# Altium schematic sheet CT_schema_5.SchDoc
size 367 x 333 mm
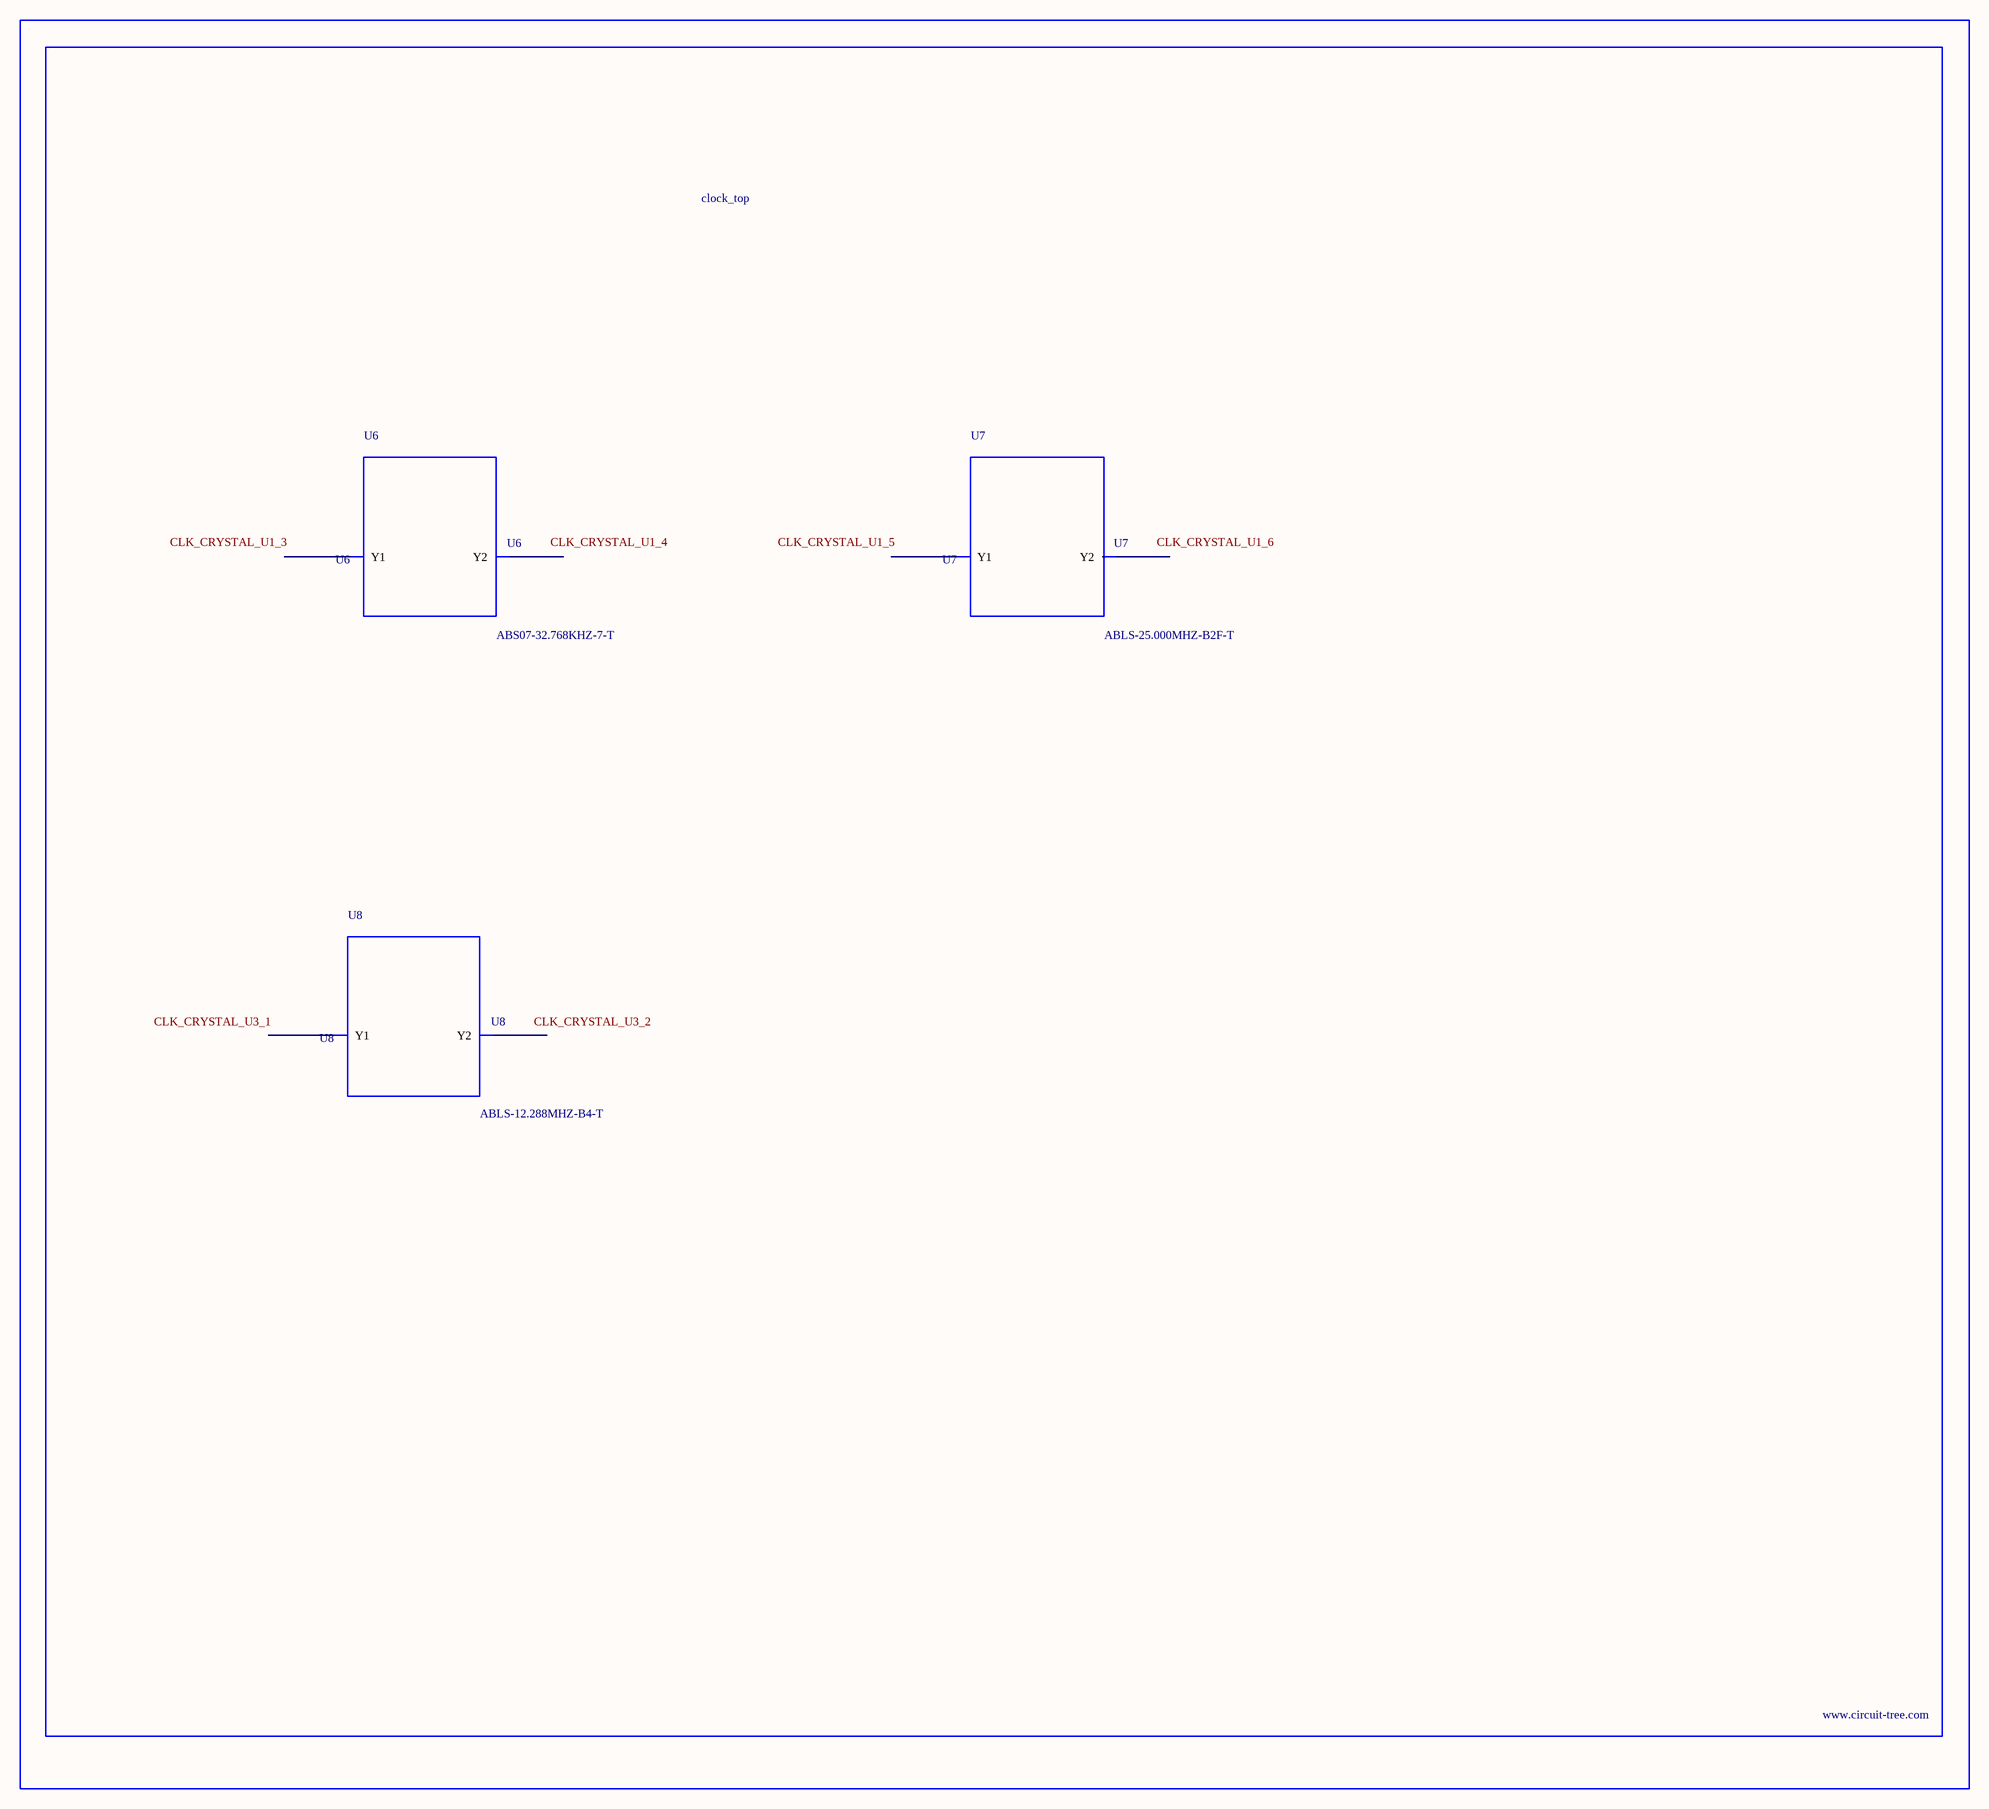
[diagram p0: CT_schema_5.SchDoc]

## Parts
BORDER4  (no value)
U6  ABS07-32.768KHZ-7-T  [ABS07-32.768KHZ-7-T]
U7  ABLS-25.000MHZ-B2F-T  [ABLS-25.000MHZ-B2F-T]
U8  ABLS-12.288MHZ-B4-T  [ABLS-12.288MHZ-B4-T]

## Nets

Not connected (* = marked no-connect by the designer): U6 1(Y1) 2(Y2); U7 1(Y1) 2(Y2); U8 1(Y1) 2(Y2)

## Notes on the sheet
- Labels drawn without touching a wire or pin: CLK_CRYSTAL_U1_3, CLK_CRYSTAL_U1_4, CLK_CRYSTAL_U1_5, CLK_CRYSTAL_U1_6, CLK_CRYSTAL_U3_1, CLK_CRYSTAL_U3_2

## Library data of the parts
BORDER4 = BORDER_PAGE4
